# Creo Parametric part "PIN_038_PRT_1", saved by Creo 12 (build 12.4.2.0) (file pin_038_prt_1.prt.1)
Units: Custom; MM, KILOGRAM, SECS

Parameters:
  PTC_WM_ITERATION = "0"
  PTC_WM_VERSION = "-.0"
  PTC_WM_LIFECYCLE_STATE = "In Work"
  PTC_WM_LIFECYCLE = "MO_CADDocument"
  PTC_WM_CREATED_BY = "Maximilian Roepper (Z0017RMS: MO)"
  PTC_WM_CREATED_ON = "18-Sep-26 11:36:42 AM"
  PTC_WM_MODIFIED_BY = "Maximilian Roepper (Z0017RMS: MO)"
  PTC_WM_MODIFIED_ON = "18-Sep-26 11:36:46 AM"
  PDMLINKNUMBER = "PDM000071455003"
  PTC_WM_NAME = "pin_038_prt_1.prt"
  PTC_WM_NUMBER = "PDM000071455003"

Other parameters: WEIGHT, WEIGHT_FACTOR, WEIGHT_ADD, _MASS_TEMP, _DIFF_TEMP, MC_ERRORS, SUPPLIER

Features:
  1. coordinate system
  2. datum plane "PRT_YZ"
  3. datum plane "PRT_XY"
  4. datum plane "PRT_XZ"
  5. coordinate system
  6. datum axis
  7. datum axis
  8. datum axis
  9. coordinate system
  10. imported feature
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
Other named items: PRT, SIEMENS_MO, DRW_VIEW_ORG, PRT_X, PRT_Y, PRT_Z, CS0, ROUGH_GROB

Layers: 00_STD_CSYS-KSYS, 01_STD_PLANES-EBENEN, 02_STD_AXES-ACHSEN, 03_STD_CSYS-KSYS, 24_IMPORT_FEAT-IMPORT_KE

Surfaces: 9 plane, 1 cylinder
